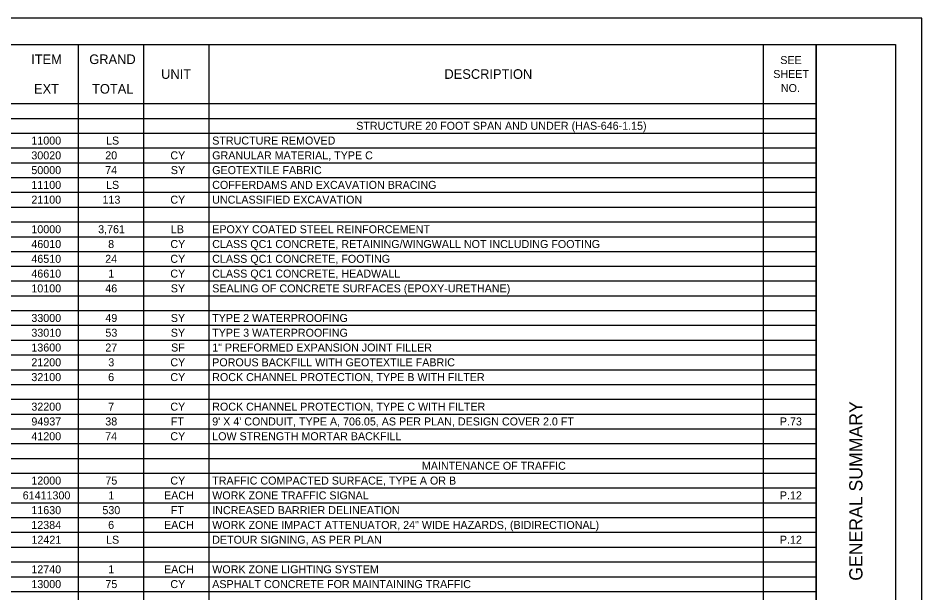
# Model space of a CAD drawing. Extents: x 0 to 34, y 0 to 22.
# Drawn here: x 16.9 to 34, y 11.11 to 22 of the extents above; entities that cross this region are included whole.
import ezdxf

# ---------------------------------------------------------------- set-up
doc = ezdxf.new("R2010")
doc.units = 0
for name, color, linetype in [('SH_Border', 7, 'Continuous'), ('SH_Cut_Line', 7, 'Continuous'), ('SH_Data', 7, 'Continuous'), ('SH_Text', 7, 'Continuous')]:
    doc.layers.add(name, color=color, linetype=linetype)

msp = doc.modelspace()

# ---------------------------------------------------------------- linework, layer by layer
at = {"layer": 'SH_Border'}
msp.add_line((32, 0.5), (32, 21.5), dxfattribs=at)
msp.add_lwpolyline([(1.5, 21.5), (33.5, 21.5), (33.5, 0.5), (1.5, 0.5)], close=True, dxfattribs=at)
at = {"layer": 'SH_Cut_Line'}
msp.add_lwpolyline([(0, 0), (34, 0), (34, 22), (0, 22)], close=True, dxfattribs=at)
at = {"layer": 'SH_Text'}
for p, q in [((1.5, 21.5), (32, 21.5)), ((18.035, 21.5), (18.035, 0.502)), ((19.27, 21.5), (19.27, 0.502)), ((20.505, 21.5), (20.505, 0.502)), ((30.995, 21.5), (30.995, 0.502)), ((32, 21.5), (32, 0.502)), ((1.5, 20.38), (32, 20.38)), ((1.5, 20.1), (32, 20.1)), ((1.5, 19.82), (32, 19.82)), ((1.5, 19.54), (32, 19.54)), ((1.5, 19.26), (32, 19.26)), ((1.5, 18.98), (32, 18.98)), ((1.5, 18.7), (32, 18.7)), ((1.5, 18.42), (32, 18.42)), ((1.5, 18.14), (32, 18.14)), ((1.5, 17.86), (32, 17.86)), ((1.5, 17.58), (32, 17.58)), ((1.5, 17.3), (32, 17.3)), ((1.5, 17.021), (32, 17.021)), ((1.5, 16.741), (32, 16.741)), ((1.5, 16.461), (32, 16.461)), ((1.5, 16.181), (32, 16.181)), ((1.5, 15.901), (32, 15.901)), ((1.5, 15.621), (32, 15.621)), ((1.5, 15.341), (32, 15.341)), ((1.5, 15.061), (32, 15.061)), ((1.5, 14.781), (32, 14.781)), ((1.5, 14.501), (32, 14.501)), ((1.5, 14.221), (32, 14.221)), ((1.5, 13.941), (32, 13.941)), ((1.5, 13.661), (32, 13.661)), ((1.5, 13.381), (32, 13.381)), ((1.5, 13.101), (32, 13.101)), ((1.5, 12.821), (32, 12.821)), ((1.5, 12.541), (32, 12.541)), ((1.5, 12.261), (32, 12.261)), ((1.5, 11.981), (32, 11.981)), ((1.5, 11.701), (32, 11.701)), ((1.5, 11.421), (32, 11.421)), ((1.5, 11.141), (32, 11.141))]:
    msp.add_line(p, q, dxfattribs=at)

# ---------------------------------------------------------------- texts
at = {"layer": 'SH_Data'}
msp.add_text('GENERAL SUMMARY', height=0.25, rotation=90, dxfattribs=at).set_placement((32.875, 11.344))
at = {"layer": 'SH_Text'}
for s, height, p in [('ITEM', 0.1818, (17.145, 21.129)), ('GRAND', 0.1818, (18.245, 21.129)), ('SEE ', 0.1515, (31.32, 21.129)), ('UNIT', 0.1818, (19.604, 20.849)), ('DESCRIPTION', 0.18181, (24.965, 20.849)), ('SHEET ', 0.1515, (31.187, 20.864)), ('EXT', 0.1818, (17.199, 20.569)), ('TOTAL', 0.1818, (18.297, 20.569)), ('NO.', 0.1515, (31.331, 20.599)), ('STRUCTURE 20 FOOT SPAN AND UNDER (HAS-646-1.15)', 0.15151, (23.296, 19.884)), ('11000', 0.1515, (17.149, 19.604)), ('LS', 0.1515, (18.562, 19.604)), ('STRUCTURE REMOVED', 0.15151, (20.571, 19.604)), ('30020', 0.1515, (17.149, 19.324)), ('20', 0.1515, (18.547, 19.324)), ('CY', 0.1515, (19.779, 19.324)), ('GRANULAR MATERIAL, TYPE C', 0.15151, (20.571, 19.324)), ('50000', 0.1515, (17.149, 19.045)), ('74', 0.1515, (18.546, 19.045)), ('SY', 0.1515, (19.788, 19.045)), ('GEOTEXTILE FABRIC', 0.15151, (20.571, 19.045)), ('11100', 0.1515, (17.149, 18.765)), ('LS', 0.1515, (18.562, 18.765)), ('COFFERDAMS AND EXCAVATION BRACING', 0.15151, (20.571, 18.765)), ('21100', 0.1515, (17.149, 18.485)), ('113', 0.1515, (18.495, 18.485)), ('CY', 0.1515, (19.779, 18.485)), ('UNCLASSIFIED EXCAVATION', 0.15151, (20.571, 18.485)), ('10000', 0.1515, (17.149, 17.925)), ('3,761', 0.1515, (18.413, 17.925)), ('LB', 0.1515, (19.788, 17.925)), ('EPOXY COATED STEEL REINFORCEMENT', 0.15151, (20.571, 17.925)), ('46010', 0.1515, (17.149, 17.645)), ('8', 0.152, (18.602, 17.645)), ('CY', 0.1515, (19.779, 17.645)), ('CLASS QC1 CONCRETE, RETAINING/WINGWALL NOT INCLUDING FOOTING', 0.15151, (20.571, 17.645)), ('46510', 0.1515, (17.149, 17.365)), ('24', 0.1515, (18.546, 17.365)), ('CY', 0.1515, (19.779, 17.365)), ('CLASS QC1 CONCRETE, FOOTING', 0.15151, (20.571, 17.365)), ('46610', 0.1515, (17.149, 17.085)), ('1', 0.152, (18.604, 17.085)), ('CY', 0.1515, (19.779, 17.085)), ('CLASS QC1 CONCRETE, HEADWALL', 0.15151, (20.571, 17.085)), ('10100', 0.1515, (17.149, 16.805)), ('46', 0.1515, (18.548, 16.805)), ('SY', 0.1515, (19.788, 16.805)), ('SEALING OF CONCRETE SURFACES (EPOXY-URETHANE)', 0.15151, (20.571, 16.805)), ('33000', 0.1515, (17.149, 16.245)), ('49', 0.1515, (18.549, 16.245)), ('SY', 0.1515, (19.788, 16.245)), ('TYPE 2 WATERPROOFING', 0.15151, (20.571, 16.245)), ('33010', 0.1515, (17.149, 15.965)), ('53', 0.1515, (18.55, 15.965)), ('SY', 0.1515, (19.788, 15.965)), ('TYPE 3 WATERPROOFING', 0.15151, (20.571, 15.965)), ('13600', 0.1515, (17.149, 15.685)), ('27', 0.1515, (18.548, 15.685)), ('SF', 0.1515, (19.793, 15.685)), ('1" PREFORMED EXPANSION JOINT FILLER', 0.15151, (20.571, 15.685)), ('21200', 0.1515, (17.149, 15.405)), ('3', 0.152, (18.604, 15.405)), ('CY', 0.1515, (19.779, 15.405)), ('POROUS BACKFILL WITH GEOTEXTILE FABRIC', 0.15151, (20.571, 15.405)), ('32100', 0.1515, (17.149, 15.125)), ('6', 0.152, (18.602, 15.125)), ('CY', 0.1515, (19.779, 15.125)), ('ROCK CHANNEL PROTECTION, TYPE B WITH FILTER', 0.15151, (20.571, 15.125)), ('32200', 0.1515, (17.149, 14.565)), ('7', 0.152, (18.603, 14.565)), ('CY', 0.1515, (19.779, 14.565)), ('ROCK CHANNEL PROTECTION, TYPE C WITH FILTER', 0.15151, (20.571, 14.565)), ('94937', 0.1515, (17.15, 14.285)), ('38', 0.1515, (18.548, 14.285)), ('FT', 0.1515, (19.786, 14.285)), ("9' X 4' CONDUIT, TYPE A, 706.05, AS PER PLAN, DESIGN COVER 2.0 FT", 0.15151, (20.571, 14.285)), ('P.73', 0.1515, (31.313, 14.285)), ('41200', 0.1515, (17.149, 14.005)), ('74', 0.1515, (18.546, 14.005)), ('CY', 0.1515, (19.779, 14.005)), ('LOW STRENGTH MORTAR BACKFILL', 0.15151, (20.571, 14.005)), ('MAINTENANCE OF TRAFFIC', 0.15151, (24.539, 13.445)), ('12000', 0.1515, (17.149, 13.165)), ('75', 0.1515, (18.55, 13.165)), ('CY', 0.1515, (19.779, 13.165)), ('TRAFFIC COMPACTED SURFACE, TYPE A OR B', 0.15151, (20.571, 13.165)), ('61411300', 0.1515, (16.985, 12.885)), ('1', 0.152, (18.604, 12.885)), ('EACH', 0.1515, (19.659, 12.885)), ('WORK ZONE TRAFFIC SIGNAL', 0.15151, (20.571, 12.885)), ('P.12', 0.1515, (31.312, 12.885)), ('11630', 0.1515, (17.149, 12.605)), ('530', 0.1515, (18.493, 12.605)), ('FT', 0.1515, (19.786, 12.605)), ('INCREASED BARRIER DELINEATION', 0.15151, (20.571, 12.605)), ('WORK ZONE IMPACT ATTENUATOR, 24" WIDE HAZARDS, (BIDIRECTIONAL)', 0.15151, (20.571, 12.325)), ('12384', 0.1515, (17.148, 12.325)), ('6', 0.152, (18.602, 12.325)), ('EACH', 0.1515, (19.659, 12.325)), ('12421', 0.1515, (17.151, 12.045)), ('LS', 0.1515, (18.562, 12.045)), ('DETOUR SIGNING, AS PER PLAN', 0.15151, (20.571, 12.045)), ('P.12', 0.1515, (31.312, 12.045)), ('12740', 0.1515, (17.149, 11.485)), ('1', 0.152, (18.604, 11.485)), ('EACH', 0.1515, (19.659, 11.485)), ('WORK ZONE LIGHTING SYSTEM', 0.15151, (20.571, 11.485)), ('13000', 0.1515, (17.149, 11.205)), ('75', 0.1515, (18.55, 11.205)), ('CY', 0.1515, (19.779, 11.205)), ('ASPHALT CONCRETE FOR MAINTAINING TRAFFIC', 0.15151, (20.571, 11.205))]:
    msp.add_text(s, height=height, dxfattribs=at).set_placement(p)

doc.saveas('drawing.dxf')
